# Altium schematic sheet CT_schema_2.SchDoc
size 276 x 169 mm
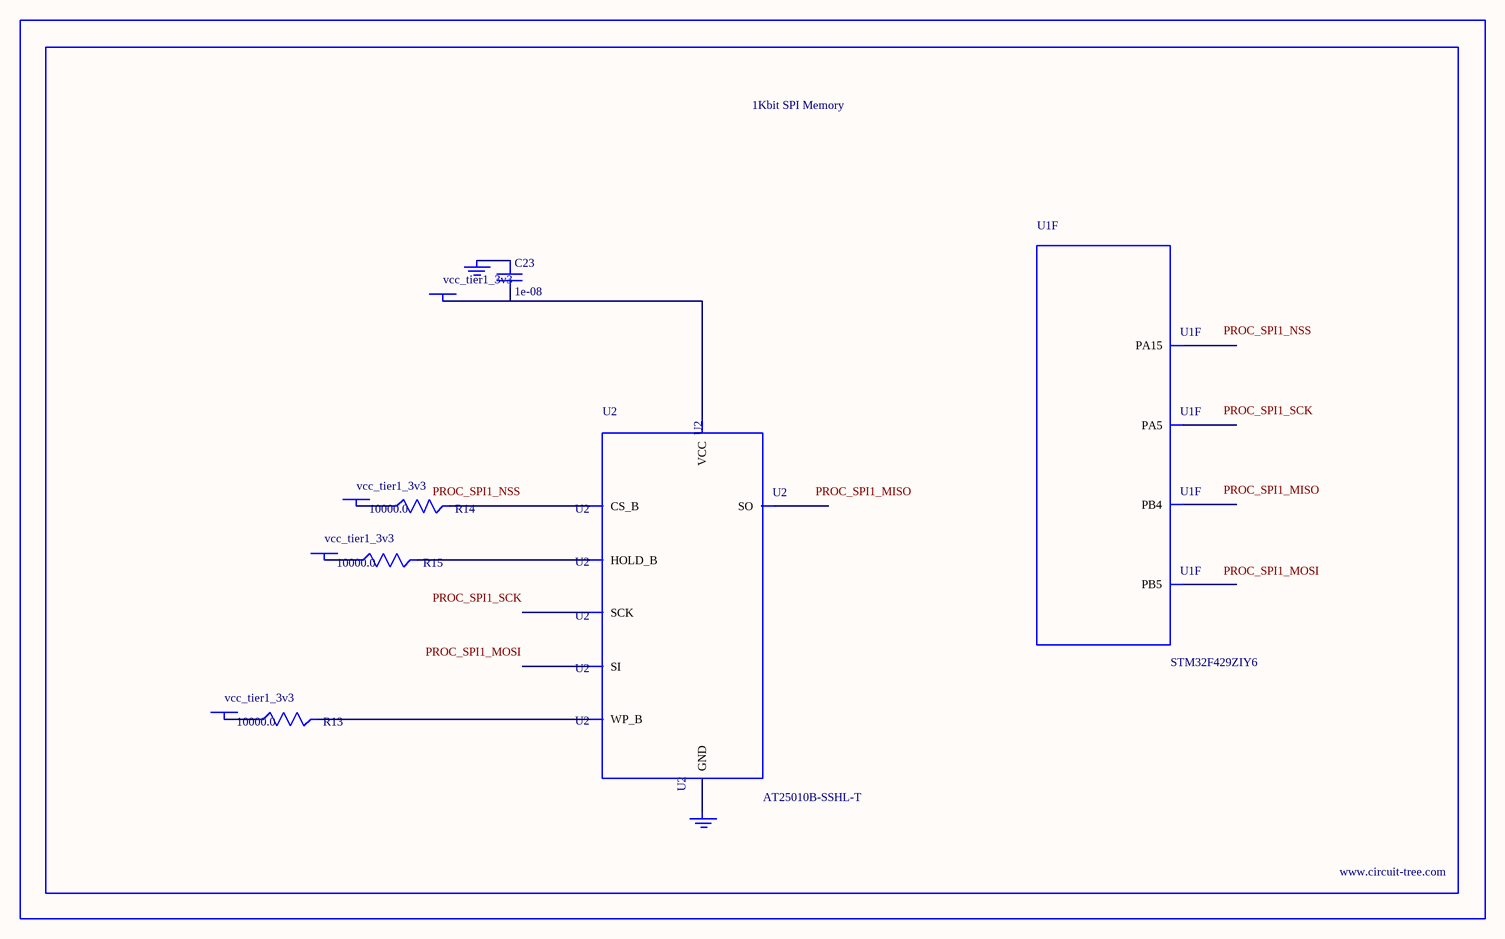
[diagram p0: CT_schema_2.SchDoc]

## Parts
BORDER1  (no value)
C23  1e-08  [C0402]
GND_INSTANCE_1_0  (no value)
GND_INSTANCE_1_1  (no value)
POWER_INSTANCE_1_0  vcc_tier1_3v3
POWER_INSTANCE_1_1  vcc_tier1_3v3
POWER_INSTANCE_1_2  vcc_tier1_3v3
POWER_INSTANCE_1_3  vcc_tier1_3v3
R13  10000.0  [R0603]
R14  10000.0  [R0603]
R15  10000.0  [R0603]
U1  STM32F429ZIY6  [WLCSP143]  (part F of 13)
U2  AT25010B-SSHL-T  [SOIC-8]

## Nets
NetC23_1: C23.1 GND_INSTANCE_1_0.0(GND)
NetC23_2: C23.2 POWER_INSTANCE_1_3.0(PWR) U2.8(VCC)
NetGND_INSTANCE_1_1_0: GND_INSTANCE_1_1.0(GND) U2.4(GND)
NetPOWER_INSTANCE_1_0_0: POWER_INSTANCE_1_0.0(PWR) R14.1
NetPOWER_INSTANCE_1_1_0: POWER_INSTANCE_1_1.0(PWR) R13.1
NetPOWER_INSTANCE_1_2_0: POWER_INSTANCE_1_2.0(PWR) R15.1
NetR13_2: R13.2 U2.3(WP_B)
NetR14_2: R14.2 U2.1(CS_B)
NetR15_2: R15.2 U2.7(HOLD_B)

Not connected (* = marked no-connect by the designer): U1 C2(PA15) C7(PB4) C8(PB5) M9(PA5); U2 2(SO) 5(SI) 6(SCK)

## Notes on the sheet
- Labels drawn without touching a wire or pin: PROC_SPI1_MISO, PROC_SPI1_MOSI, PROC_SPI1_NSS, PROC_SPI1_SCK

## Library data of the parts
BORDER1 = BORDER_PAGE1
C23 = C0402C103K3RAC
GND_INSTANCE_1_0 GND_INSTANCE_1_1 = GND
POWER_INSTANCE_1_0-POWER_INSTANCE_1_3 = PWR
R13-R15 = RC0603JR-0710KL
